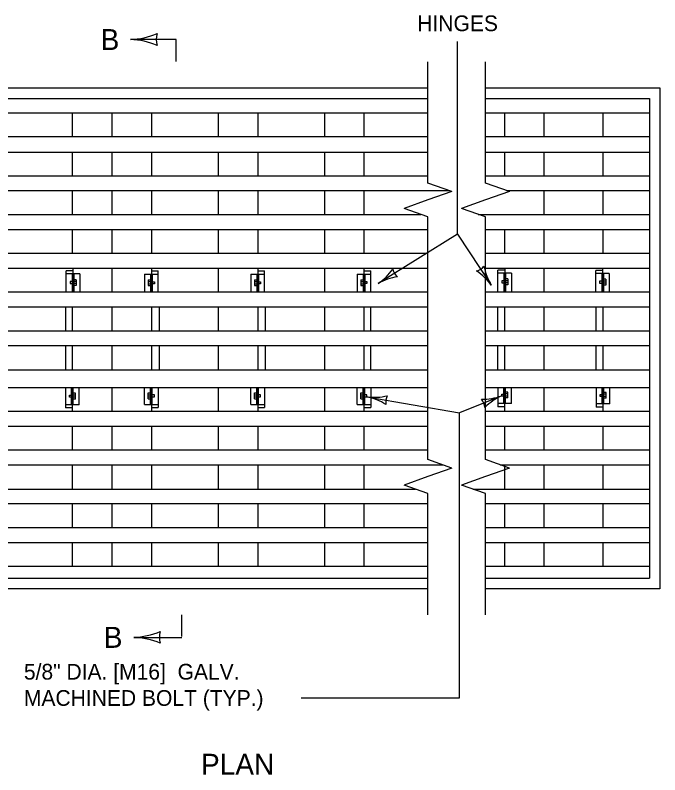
# Model space of a CAD drawing. Extents: x 49991.4 to 50021, y 49987.6 to 50011.4.
# Drawn here: x 50003.606 to 50006.064, y 49994.163 to 49997.058 of the extents above; entities that cross this region are included whole.
import ezdxf

# ---------------------------------------------------------------- set-up
doc = ezdxf.new("R2010")
doc.units = 0
for name, color, linetype in [('Level 1', 7, 'Continuous'), ('Level 2', 7, 'Continuous'), ('Level 3', 7, 'Continuous'), ('Level 6', 7, 'Continuous')]:
    doc.layers.add(name, color=color, linetype=linetype)

msp = doc.modelspace()

# ---------------------------------------------------------------- linework, layer by layer
at = {"layer": 'Level 1'}
for p, q in [((50002.9371, 49996.781), (50005.18, 49996.781)), ((50005.3989, 49996.781), (50006.064, 49996.781)), ((50006.064, 49996.781), (50006.064, 49994.8717)), ((50002.9379, 49996.741), (50005.1783, 49996.741)), ((50005.3989, 49996.741), (50006.024, 49996.741)), ((50006.024, 49996.741), (50006.024, 49994.9122)), ((50005.18, 49996.6851), (50002.9379, 49996.6851)), ((50003.8237, 49996.6851), (50003.8237, 49996.5943)), ((50003.9745, 49996.6851), (50003.9745, 49996.5943)), ((50004.1253, 49996.6851), (50004.1253, 49996.5943)), ((50004.3795, 49996.6851), (50004.3795, 49996.5943)), ((50004.5306, 49996.6851), (50004.5306, 49996.5943)), ((50004.7848, 49996.6851), (50004.7848, 49996.5943)), ((50004.9356, 49996.6851), (50004.9356, 49996.5943)), ((50006.024, 49996.6851), (50005.3989, 49996.6851)), ((50005.4725, 49996.5943), (50005.4725, 49996.6851)), ((50005.6234, 49996.5943), (50005.6234, 49996.6851)), ((50005.8476, 49996.5943), (50005.8476, 49996.6851)), ((50005.1785, 49996.5943), (50002.9379, 49996.5943)), ((50006.024, 49996.5943), (50005.3989, 49996.5943)), ((50002.9379, 49996.5364), (50005.1786, 49996.5364)), ((50003.8237, 49996.5364), (50003.8237, 49996.4463)), ((50003.9745, 49996.5364), (50003.9745, 49996.4463)), ((50004.1253, 49996.5364), (50004.1253, 49996.4463)), ((50004.3795, 49996.5364), (50004.3795, 49996.4463)), ((50004.5306, 49996.5364), (50004.5306, 49996.4463)), ((50004.7848, 49996.5364), (50004.7848, 49996.4463)), ((50004.9356, 49996.5364), (50004.9356, 49996.4463)), ((50005.3989, 49996.5364), (50006.024, 49996.5364)), ((50005.4725, 49996.4463), (50005.4725, 49996.5364)), ((50005.6234, 49996.4463), (50005.6234, 49996.5364)), ((50005.8476, 49996.4463), (50005.8476, 49996.5364)), ((50002.9379, 49996.4463), (50005.18, 49996.4463)), ((50005.3989, 49996.4463), (50006.024, 49996.4463)), ((50003.0192, 49996.3895), (50005.2621, 49996.3895)), ((50003.8237, 49996.3895), (50003.8237, 49996.2987)), ((50003.9745, 49996.3895), (50003.9745, 49996.2987)), ((50004.1253, 49996.3895), (50004.1253, 49996.2987)), ((50004.3795, 49996.3895), (50004.3795, 49996.2987)), ((50004.5306, 49996.3895), (50004.5306, 49996.2987)), ((50004.7848, 49996.3895), (50004.7848, 49996.2987)), ((50004.9356, 49996.3895), (50004.9356, 49996.2987)), ((50005.481, 49996.3895), (50006.024, 49996.3895)), ((50005.6234, 49996.2987), (50005.6234, 49996.3895)), ((50005.8476, 49996.2987), (50005.8476, 49996.3895)), ((50002.9097, 49996.2987), (50005.1526, 49996.2987)), ((50005.3715, 49996.2987), (50006.024, 49996.2987)), ((50002.9371, 49996.2418), (50005.1786, 49996.2418)), ((50003.8237, 49996.2418), (50003.8237, 49996.1509)), ((50003.9745, 49996.2418), (50003.9745, 49996.1509)), ((50004.1253, 49996.2418), (50004.1253, 49996.1509)), ((50004.3795, 49996.2418), (50004.3795, 49996.1509)), ((50004.5306, 49996.2418), (50004.5306, 49996.1509)), ((50004.7848, 49996.2418), (50004.7848, 49996.1509)), ((50004.9356, 49996.2418), (50004.9356, 49996.1509)), ((50005.3989, 49996.2418), (50006.024, 49996.2418)), ((50005.4725, 49996.1509), (50005.4725, 49996.2418)), ((50005.6234, 49996.1509), (50005.6234, 49996.2418)), ((50005.8476, 49996.1509), (50005.8476, 49996.2418)), ((50002.9371, 49996.1509), (50005.1791, 49996.1509)), ((50005.3989, 49996.1509), (50006.024, 49996.1509)), ((50002.9371, 49996.0941), (50005.1793, 49996.0941)), ((50003.8004, 49996.0031), (50003.8004, 49996.0839)), ((50003.8263, 49996.0839), (50003.8005, 49996.0839)), ((50003.8263, 49996.0941), (50003.8263, 49996.0031)), ((50003.9745, 49996.0941), (50003.9745, 49996.0031)), ((50004.1253, 49996.0941), (50004.1253, 49996.0031)), ((50004.1253, 49996.0833), (50004.1511, 49996.0833)), ((50004.1512, 49996.0031), (50004.1512, 49996.0833)), ((50004.3795, 49996.0941), (50004.3795, 49996.0031)), ((50004.5306, 49996.0941), (50004.5306, 49996.0031)), ((50004.5306, 49996.0833), (50004.5564, 49996.0833)), ((50004.5565, 49996.0031), (50004.5565, 49996.0833)), ((50004.7848, 49996.0941), (50004.7848, 49996.0031)), ((50004.9356, 49996.0941), (50004.9356, 49996.0031)), ((50004.9356, 49996.0835), (50004.9614, 49996.0835)), ((50004.9615, 49996.0031), (50004.9615, 49996.0835)), ((50005.3989, 49996.0941), (50006.024, 49996.0941)), ((50005.4466, 49996.0031), (50005.4466, 49996.0865)), ((50005.4983, 49996.0745), (50005.4466, 49996.0745)), ((50005.4725, 49996.0865), (50005.4467, 49996.0865)), ((50005.4695, 49996.0745), (50005.4695, 49996.0031)), ((50005.4725, 49996.0941), (50005.4725, 49996.0031)), ((50005.4755, 49996.0745), (50005.4755, 49996.0031)), ((50005.4983, 49996.0745), (50005.4983, 49996.0031)), ((50005.6234, 49996.0031), (50005.6234, 49996.0941)), ((50005.8197, 49996.0031), (50005.8197, 49996.0854)), ((50005.8714, 49996.0734), (50005.8197, 49996.0734)), ((50005.8456, 49996.0854), (50005.8198, 49996.0854)), ((50005.8426, 49996.0734), (50005.8426, 49996.0031)), ((50005.8456, 49996.0941), (50005.8456, 49996.0031)), ((50005.8486, 49996.0734), (50005.8486, 49996.0031)), ((50005.8714, 49996.0734), (50005.8714, 49996.0031)), ((50003.8521, 49996.0719), (50003.8004, 49996.0719)), ((50003.8233, 49996.0719), (50003.8233, 49996.0031)), ((50003.8293, 49996.0719), (50003.8293, 49996.0031)), ((50003.8383, 49996.0501), (50003.8293, 49996.0501)), ((50003.8383, 49996.0501), (50003.8383, 49996.0279)), ((50003.8521, 49996.0719), (50003.8521, 49996.0031)), ((50004.0995, 49996.0713), (50004.1511, 49996.0713)), ((50004.0995, 49996.0713), (50004.0995, 49996.0031)), ((50004.1133, 49996.0495), (50004.1133, 49996.0273)), ((50004.1133, 49996.0495), (50004.1223, 49996.0495)), ((50004.1223, 49996.0713), (50004.1223, 49996.0031)), ((50004.1283, 49996.0713), (50004.1283, 49996.0031)), ((50004.5048, 49996.0713), (50004.5565, 49996.0713)), ((50004.5048, 49996.0713), (50004.5048, 49996.0031)), ((50004.5186, 49996.0495), (50004.5186, 49996.0273)), ((50004.5186, 49996.0495), (50004.5276, 49996.0495)), ((50004.5276, 49996.0713), (50004.5276, 49996.0031)), ((50004.5336, 49996.0713), (50004.5336, 49996.0031)), ((50004.9098, 49996.0715), (50004.9614, 49996.0715)), ((50004.9098, 49996.0715), (50004.9098, 49996.0031)), ((50004.9236, 49996.0497), (50004.9236, 49996.0275)), ((50004.9236, 49996.0497), (50004.9326, 49996.0497)), ((50004.9326, 49996.0715), (50004.9326, 49996.0031)), ((50004.9386, 49996.0715), (50004.9386, 49996.0031)), ((50005.4695, 49996.0456), (50005.4612, 49996.0456)), ((50005.4612, 49996.0456), (50005.4612, 49996.0379)), ((50005.4845, 49996.0527), (50005.4755, 49996.0527)), ((50005.4845, 49996.0459), (50005.4755, 49996.0459)), ((50005.4845, 49996.0527), (50005.4845, 49996.0305)), ((50005.8426, 49996.0445), (50005.8343, 49996.0445)), ((50005.8343, 49996.0445), (50005.8343, 49996.0368)), ((50005.8576, 49996.0516), (50005.8486, 49996.0516)), ((50005.8576, 49996.0448), (50005.8486, 49996.0448)), ((50005.8576, 49996.0516), (50005.8576, 49996.0294)), ((50003.8233, 49996.043), (50003.815, 49996.043)), ((50003.815, 49996.043), (50003.815, 49996.0353)), ((50003.815, 49996.0353), (50003.8233, 49996.0353)), ((50003.8381, 49996.0433), (50003.8293, 49996.0433)), ((50003.8383, 49996.0349), (50003.8293, 49996.0349)), ((50003.8383, 49996.0279), (50003.8293, 49996.0279)), ((50004.1133, 49996.0427), (50004.1223, 49996.0427)), ((50004.1133, 49996.0343), (50004.1223, 49996.0343)), ((50004.1133, 49996.0273), (50004.1223, 49996.0273)), ((50004.1283, 49996.0424), (50004.1366, 49996.0424)), ((50004.1366, 49996.0347), (50004.1283, 49996.0347)), ((50004.1366, 49996.0424), (50004.1366, 49996.0347)), ((50004.5186, 49996.0343), (50004.5276, 49996.0343)), ((50004.5186, 49996.0273), (50004.5276, 49996.0273)), ((50004.5188, 49996.0427), (50004.5276, 49996.0427)), ((50004.5336, 49996.0424), (50004.5419, 49996.0424)), ((50004.5419, 49996.0347), (50004.5336, 49996.0347)), ((50004.5419, 49996.0424), (50004.5419, 49996.0347)), ((50004.9236, 49996.0429), (50004.9326, 49996.0429)), ((50004.9236, 49996.0345), (50004.9326, 49996.0345)), ((50004.9236, 49996.0275), (50004.9326, 49996.0275)), ((50004.9386, 49996.0426), (50004.9469, 49996.0426)), ((50004.9469, 49996.0349), (50004.9386, 49996.0349)), ((50004.9469, 49996.0426), (50004.9469, 49996.0349)), ((50005.4612, 49996.0379), (50005.4695, 49996.0379)), ((50005.4845, 49996.0375), (50005.4755, 49996.0375)), ((50005.4845, 49996.0305), (50005.4755, 49996.0305)), ((50005.8343, 49996.0368), (50005.8426, 49996.0368)), ((50005.8576, 49996.0364), (50005.8486, 49996.0364)), ((50005.8576, 49996.0294), (50005.8486, 49996.0294)), ((50002.9371, 49996.0031), (50005.1797, 49996.0031)), ((50005.3989, 49996.0031), (50006.024, 49996.0031)), ((50002.9371, 49995.9464), (50005.18, 49995.9464)), ((50003.7979, 49995.9464), (50003.7979, 49995.8554)), ((50003.8237, 49995.9464), (50003.8237, 49995.8554)), ((50003.9745, 49995.9464), (50003.9745, 49995.8554)), ((50004.1253, 49995.9464), (50004.1253, 49995.8554)), ((50004.1544, 49995.9464), (50004.1544, 49995.8554)), ((50004.3795, 49995.9464), (50004.3795, 49995.8554)), ((50004.5306, 49995.9464), (50004.5306, 49995.8554)), ((50004.5597, 49995.9464), (50004.5597, 49995.8554)), ((50004.7848, 49995.9464), (50004.7848, 49995.8554)), ((50004.9356, 49995.9464), (50004.9356, 49995.8554)), ((50004.9615, 49995.8554), (50004.9615, 49995.9464)), ((50005.3989, 49995.9464), (50006.024, 49995.9464)), ((50005.4467, 49995.8554), (50005.4467, 49995.9464)), ((50005.4725, 49995.8554), (50005.4725, 49995.9464)), ((50005.6234, 49995.8554), (50005.6234, 49995.9464)), ((50005.8218, 49995.8554), (50005.8218, 49995.9464)), ((50005.8476, 49995.8554), (50005.8476, 49995.9464)), ((50002.9371, 49995.8554), (50005.18, 49995.8554)), ((50005.3989, 49995.8554), (50006.024, 49995.8554)), ((50002.9371, 49995.7987), (50005.1793, 49995.7987)), ((50003.7979, 49995.7987), (50003.7979, 49995.7061)), ((50003.8237, 49995.7987), (50003.8237, 49995.7061)), ((50003.9745, 49995.7987), (50003.9745, 49995.7061)), ((50004.1253, 49995.7987), (50004.1253, 49995.7061)), ((50004.1544, 49995.7987), (50004.1544, 49995.7061)), ((50004.3795, 49995.7987), (50004.3795, 49995.7061)), ((50004.5306, 49995.7987), (50004.5306, 49995.7061)), ((50004.5597, 49995.7987), (50004.5597, 49995.7061)), ((50004.7848, 49995.7987), (50004.7848, 49995.7061)), ((50004.9356, 49995.7987), (50004.9356, 49995.7061)), ((50004.9615, 49995.7061), (50004.9615, 49995.7987)), ((50005.3989, 49995.7987), (50006.024, 49995.7987)), ((50005.4467, 49995.7061), (50005.4467, 49995.7987)), ((50005.4725, 49995.7061), (50005.4725, 49995.7987)), ((50005.6234, 49995.7061), (50005.6234, 49995.7987)), ((50005.8218, 49995.7061), (50005.8218, 49995.7987)), ((50005.8476, 49995.7061), (50005.8476, 49995.7987)), ((50002.9371, 49995.7061), (50005.1793, 49995.7061)), ((50005.3989, 49995.7061), (50006.024, 49995.7061)), ((50002.9371, 49995.6395), (50005.1793, 49995.6395)), ((50003.7978, 49995.6395), (50003.7978, 49995.5611)), ((50003.8207, 49995.5731), (50003.8207, 49995.6395)), ((50003.8237, 49995.6395), (50003.8237, 49995.5486)), ((50003.8267, 49995.5731), (50003.8267, 49995.6395)), ((50003.8495, 49995.5731), (50003.8495, 49995.6395)), ((50003.9745, 49995.6395), (50003.9745, 49995.5486)), ((50004.0995, 49995.5743), (50004.0995, 49995.6395)), ((50004.1223, 49995.5743), (50004.1223, 49995.6395)), ((50004.1253, 49995.6395), (50004.1253, 49995.5486)), ((50004.1283, 49995.5743), (50004.1283, 49995.6395)), ((50004.1512, 49995.6395), (50004.1512, 49995.5623)), ((50004.3795, 49995.6395), (50004.3795, 49995.5486)), ((50004.5048, 49995.5743), (50004.5048, 49995.6395)), ((50004.5276, 49995.5743), (50004.5276, 49995.6395)), ((50004.5306, 49995.6395), (50004.5306, 49995.5486)), ((50004.5336, 49995.5743), (50004.5336, 49995.6395)), ((50004.5565, 49995.6395), (50004.5565, 49995.5623)), ((50004.7848, 49995.6395), (50004.7848, 49995.5486)), ((50004.9098, 49995.5743), (50004.9098, 49995.6395)), ((50004.9326, 49995.5743), (50004.9326, 49995.6395)), ((50004.9356, 49995.6395), (50004.9356, 49995.5486)), ((50004.9386, 49995.5743), (50004.9386, 49995.6395)), ((50004.9615, 49995.6395), (50004.9615, 49995.5623)), ((50005.3989, 49995.6395), (50006.024, 49995.6395)), ((50005.4466, 49995.6395), (50005.4466, 49995.5655)), ((50005.4695, 49995.5775), (50005.4695, 49995.6395)), ((50005.4725, 49995.5486), (50005.4725, 49995.6395)), ((50005.4755, 49995.5775), (50005.4755, 49995.6395)), ((50005.4983, 49995.5775), (50005.4983, 49995.6395)), ((50005.6234, 49995.5486), (50005.6234, 49995.6395)), ((50005.8217, 49995.6395), (50005.8217, 49995.5642)), ((50005.8446, 49995.5762), (50005.8446, 49995.6395)), ((50005.8476, 49995.5486), (50005.8476, 49995.6395)), ((50005.8506, 49995.5762), (50005.8506, 49995.6395)), ((50005.8734, 49995.5762), (50005.8734, 49995.6395)), ((50003.8124, 49995.602), (50003.8124, 49995.6097)), ((50003.8124, 49995.6097), (50003.8207, 49995.6097)), ((50003.8357, 49995.6171), (50003.8267, 49995.6171)), ((50003.8357, 49995.6101), (50003.8267, 49995.6101)), ((50003.8357, 49995.5949), (50003.8357, 49995.6171)), ((50004.1133, 49995.5961), (50004.1133, 49995.6183)), ((50004.1133, 49995.6183), (50004.1223, 49995.6183)), ((50004.1133, 49995.6113), (50004.1223, 49995.6113)), ((50004.1366, 49995.6109), (50004.1283, 49995.6109)), ((50004.1366, 49995.6032), (50004.1366, 49995.6109)), ((50004.5186, 49995.5961), (50004.5186, 49995.6183)), ((50004.5186, 49995.6183), (50004.5276, 49995.6183)), ((50004.5186, 49995.6113), (50004.5276, 49995.6113)), ((50004.5419, 49995.6109), (50004.5336, 49995.6109)), ((50004.5419, 49995.6032), (50004.5419, 49995.6109)), ((50004.9236, 49995.5961), (50004.9236, 49995.6183)), ((50004.9236, 49995.6183), (50004.9326, 49995.6183)), ((50004.9236, 49995.6113), (50004.9326, 49995.6113)), ((50004.9469, 49995.6109), (50004.9386, 49995.6109)), ((50004.9469, 49995.6032), (50004.9469, 49995.6109)), ((50005.4612, 49995.6064), (50005.4612, 49995.6141)), ((50005.4612, 49995.6141), (50005.4695, 49995.6141)), ((50005.4845, 49995.6215), (50005.4755, 49995.6215)), ((50005.4845, 49995.6145), (50005.4755, 49995.6145)), ((50005.4845, 49995.5993), (50005.4845, 49995.6215)), ((50005.8363, 49995.6051), (50005.8363, 49995.6128)), ((50005.8363, 49995.6128), (50005.8446, 49995.6128)), ((50005.8596, 49995.6202), (50005.8506, 49995.6202)), ((50005.8596, 49995.6132), (50005.8506, 49995.6132)), ((50005.8596, 49995.598), (50005.8596, 49995.6202)), ((50003.8207, 49995.602), (50003.8124, 49995.602)), ((50003.8355, 49995.6017), (50003.8267, 49995.6017)), ((50003.8357, 49995.5949), (50003.8267, 49995.5949)), ((50004.1133, 49995.6029), (50004.1223, 49995.6029)), ((50004.1133, 49995.5961), (50004.1223, 49995.5961)), ((50004.1283, 49995.6032), (50004.1366, 49995.6032)), ((50004.5186, 49995.5961), (50004.5276, 49995.5961)), ((50004.5188, 49995.6029), (50004.5276, 49995.6029)), ((50004.5336, 49995.6032), (50004.5419, 49995.6032)), ((50004.9236, 49995.6029), (50004.9326, 49995.6029)), ((50004.9236, 49995.5961), (50004.9326, 49995.5961)), ((50004.9386, 49995.6032), (50004.9469, 49995.6032)), ((50005.4695, 49995.6064), (50005.4612, 49995.6064)), ((50005.4845, 49995.6061), (50005.4755, 49995.6061)), ((50005.4845, 49995.5993), (50005.4755, 49995.5993)), ((50005.8446, 49995.6051), (50005.8363, 49995.6051)), ((50005.8596, 49995.6048), (50005.8506, 49995.6048)), ((50005.8596, 49995.598), (50005.8506, 49995.598)), ((50003.8495, 49995.5731), (50003.7978, 49995.5731)), ((50003.8237, 49995.5611), (50003.7979, 49995.5611)), ((50004.0995, 49995.5743), (50004.1512, 49995.5743)), ((50004.1253, 49995.5623), (50004.1511, 49995.5623)), ((50004.5048, 49995.5743), (50004.5564, 49995.5743)), ((50004.5306, 49995.5623), (50004.5564, 49995.5623)), ((50004.9098, 49995.5743), (50004.9614, 49995.5743)), ((50004.9356, 49995.5623), (50004.9614, 49995.5623)), ((50005.4983, 49995.5775), (50005.4467, 49995.5775)), ((50005.4725, 49995.5655), (50005.4467, 49995.5655)), ((50005.8734, 49995.5762), (50005.8217, 49995.5762)), ((50005.8476, 49995.5642), (50005.8218, 49995.5642)), ((50002.9371, 49995.5486), (50005.1793, 49995.5486)), ((50005.3989, 49995.5486), (50006.024, 49995.5486)), ((50002.9371, 49995.4918), (50005.1793, 49995.4918)), ((50003.8237, 49995.4918), (50003.8237, 49995.4009)), ((50003.9745, 49995.4918), (50003.9745, 49995.4009)), ((50004.1253, 49995.4918), (50004.1253, 49995.4009)), ((50004.3795, 49995.4918), (50004.3795, 49995.4009)), ((50004.5306, 49995.4918), (50004.5306, 49995.4009)), ((50004.7848, 49995.4918), (50004.7848, 49995.4009)), ((50004.9356, 49995.4918), (50004.9356, 49995.4009)), ((50005.3989, 49995.4918), (50006.024, 49995.4918)), ((50005.4725, 49995.4009), (50005.4725, 49995.4918)), ((50005.6234, 49995.4009), (50005.6234, 49995.4918)), ((50005.8476, 49995.4009), (50005.8476, 49995.4918)), ((50002.9371, 49995.4009), (50005.1793, 49995.4009)), ((50005.3989, 49995.4009), (50006.024, 49995.4009)), ((50002.9938, 49995.3441), (50005.2367, 49995.3441)), ((50003.8237, 49995.3441), (50003.8237, 49995.2515)), ((50003.9745, 49995.3441), (50003.9745, 49995.2515)), ((50004.1253, 49995.3441), (50004.1253, 49995.2515)), ((50004.3795, 49995.3441), (50004.3795, 49995.2515)), ((50004.5306, 49995.3441), (50004.5306, 49995.2515)), ((50004.7848, 49995.3441), (50004.7848, 49995.2515)), ((50004.9356, 49995.3441), (50004.9356, 49995.2515)), ((50005.4556, 49995.3441), (50006.024, 49995.3441)), ((50005.4725, 49995.2515), (50005.4725, 49995.3441)), ((50005.6234, 49995.2515), (50005.6234, 49995.3441)), ((50005.8476, 49995.2515), (50005.8476, 49995.3441)), ((50002.8894, 49995.2515), (50005.1323, 49995.2515)), ((50005.3512, 49995.2515), (50006.024, 49995.2515)), ((50002.9371, 49995.1965), (50005.18, 49995.1965)), ((50003.8237, 49995.1965), (50003.8237, 49995.1054)), ((50003.9745, 49995.1965), (50003.9745, 49995.1054)), ((50004.1253, 49995.1965), (50004.1253, 49995.1054)), ((50004.3795, 49995.1965), (50004.3795, 49995.1054)), ((50004.5306, 49995.1965), (50004.5306, 49995.1054)), ((50004.7848, 49995.1965), (50004.7848, 49995.1054)), ((50004.9356, 49995.1965), (50004.9356, 49995.1054)), ((50005.3989, 49995.1965), (50006.024, 49995.1965)), ((50005.4725, 49995.1054), (50005.4725, 49995.1965)), ((50005.6234, 49995.1054), (50005.6234, 49995.1965)), ((50005.8476, 49995.1054), (50005.8476, 49995.1965)), ((50002.9371, 49995.1054), (50005.18, 49995.1054)), ((50005.3989, 49995.1054), (50006.024, 49995.1054)), ((50002.9371, 49995.0478), (50005.18, 49995.0478)), ((50003.8237, 49995.0478), (50003.8237, 49994.9577)), ((50003.9745, 49995.0478), (50003.9745, 49994.9577)), ((50004.1253, 49995.0478), (50004.1253, 49994.9577)), ((50004.3795, 49995.0478), (50004.3795, 49994.9577)), ((50004.5306, 49995.0478), (50004.5306, 49994.9577)), ((50004.7848, 49995.0478), (50004.7848, 49994.9577)), ((50004.9356, 49995.0478), (50004.9356, 49994.9577)), ((50005.3989, 49995.0478), (50006.024, 49995.0478)), ((50005.4725, 49994.9577), (50005.4725, 49995.0478)), ((50005.6234, 49994.9577), (50005.6234, 49995.0478)), ((50005.8476, 49994.9577), (50005.8476, 49995.0478)), ((50002.9371, 49994.9577), (50005.18, 49994.9577)), ((50005.3989, 49994.9577), (50006.024, 49994.9577)), ((50002.9371, 49994.9122), (50005.18, 49994.9122)), ((50005.3989, 49994.9122), (50006.024, 49994.9122)), ((50002.9371, 49994.8722), (50005.18, 49994.8722)), ((50005.3989, 49994.8722), (50006.064, 49994.8722))]:
    msp.add_line(p, q, dxfattribs=at)
at = {"layer": 'Level 3'}
for p, q in [((50005.2926, 49996.2239), (50005.2926, 49996.9574)), ((50005.2926, 49996.2239), (50004.99, 49996.0354)), ((50005.2926, 49996.2239), (50005.4214, 49996.0289)), ((50004.9469, 49995.6032), (50005.2995, 49995.542)), ((50005.4612, 49995.6072), (50005.2995, 49995.542)), ((50005.2995, 49994.4555), (50005.2995, 49995.542)), ((50004.6963, 49994.4555), (50005.2995, 49994.4555))]:
    msp.add_line(p, q, dxfattribs=at)
for centre, radius, start, end in [((50005.3507, 49996.1359), 0.0548, 285.5841, 321.3065), ((50005.6118, 49996.1437), 0.2223, 190.9013, 211.0848), ((50004.8572, 49996.2268), 0.233, 304.7475, 323.9974), ((50005.0988, 49996.1032), 0.0548, 194.059, 229.7814), ((50005.2335, 49995.8911), 0.233, 36.2726, 55.5224), ((50005.0996, 49995.842), 0.2223, 99.3762, 119.5597), ((50004.9734, 49995.8347), 0.233, 263.4704, 282.7203), ((50004.9017, 49995.3855), 0.2223, 58.0991, 78.2826), ((50005.0734, 49995.5824), 0.0548, 152.7819, 188.5043), ((50005.3866, 49995.8166), 0.2223, 269.4161, 289.5996), ((50005.3422, 49995.5593), 0.0548, 4.0989, 39.8213), ((50005.5588, 49995.3957), 0.233, 114.7874, 134.0372)]:
    msp.add_arc(centre, radius, start, end, dxfattribs=at)
at = {"layer": 'Level 6'}
for p, q in [((50004.2193, 49996.9655), (50004.0457, 49996.9655)), ((50004.2193, 49996.8814), (50004.2193, 49996.9655)), ((50005.18, 49996.4186), (50005.18, 49996.881)), ((50005.3989, 49996.4186), (50005.3989, 49996.881)), ((50005.2714, 49996.3862), (50005.18, 49996.4186)), ((50005.4903, 49996.3862), (50005.3989, 49996.4186)), ((50005.2714, 49996.3862), (50005.18, 49996.3538)), ((50005.4903, 49996.3862), (50005.3989, 49996.3538)), ((50005.18, 49996.3538), (50005.0886, 49996.3214)), ((50005.3989, 49996.3538), (50005.3075, 49996.3214)), ((50005.18, 49996.289), (50005.0886, 49996.3214)), ((50005.3989, 49996.289), (50005.3075, 49996.3214)), ((50005.18, 49995.3642), (50005.18, 49996.289)), ((50005.3989, 49995.3642), (50005.3989, 49996.289)), ((50005.2714, 49995.3318), (50005.18, 49995.3642)), ((50005.4903, 49995.3318), (50005.3989, 49995.3642)), ((50005.2714, 49995.3318), (50005.18, 49995.2994)), ((50005.4903, 49995.3318), (50005.3989, 49995.2994)), ((50005.18, 49995.2994), (50005.0886, 49995.267)), ((50005.3989, 49995.2994), (50005.3075, 49995.267)), ((50005.18, 49995.2346), (50005.0886, 49995.267)), ((50005.3989, 49995.2346), (50005.3075, 49995.267)), ((50005.18, 49994.7722), (50005.18, 49995.2346)), ((50005.3989, 49994.7722), (50005.3989, 49995.2346)), ((50004.2414, 49994.6897), (50004.2414, 49994.7722)), ((50004.0578, 49994.6866), (50004.2414, 49994.6866))]:
    msp.add_line(p, q, dxfattribs=at)
for centre, radius, start, end in [((50004.0303, 49997.2758), 0.3107, 272.8273, 292.0772), ((50004.2166, 49996.9655), 0.073, 162.1388, 197.8612), ((50004.0334, 49996.6693), 0.2964, 67.456, 87.6395), ((50004.0424, 49994.9969), 0.3107, 272.8273, 292.0772), ((50004.0455, 49994.3904), 0.2964, 67.456, 87.6395), ((50004.2287, 49994.6866), 0.073, 162.1388, 197.8612)]:
    msp.add_arc(centre, radius, start, end, dxfattribs=at)

# ---------------------------------------------------------------- texts
at = {"layer": 'Level 2'}
for s, height, p in [('HINGES', 0.06, (50005.1391, 49996.9974)), ('B', 0.08, (50003.9316, 49996.9255)), ('B', 0.08, (50003.9437, 49994.6466)), ('5/8" DIA. [M16]  GALV.', 0.06, (50003.6391, 49994.5255)), ('MACHINED BOLT (TYP.)', 0.06, (50003.6391, 49994.4255)), ('PLAN', 0.08, (50004.3144, 49994.1626))]:
    msp.add_text(s, height=height, dxfattribs=at).set_placement(p)

doc.saveas('drawing.dxf')
